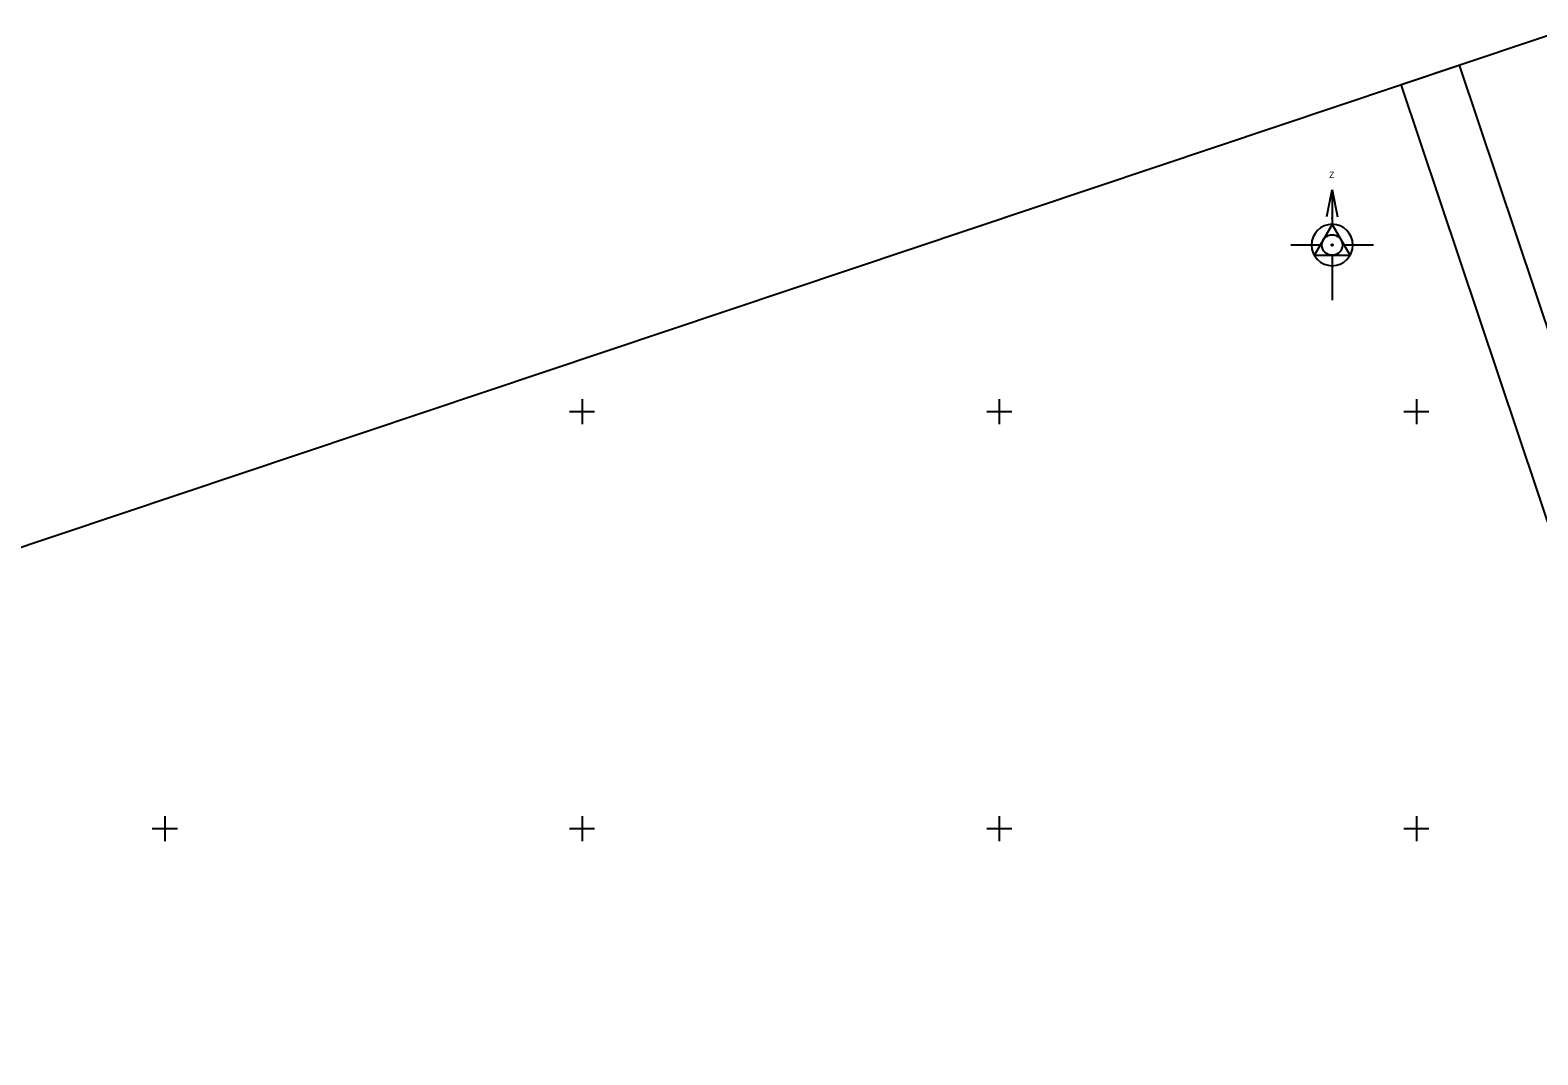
# Model space of a CAD drawing. Extents: x 469981 to 472086, y 246785 to 247785.
# Drawn here: x 470833.9 to 471014.5, y 247272.9 to 247395.7 of the extents above; entities that cross this region are included whole.
import ezdxf

# ---------------------------------------------------------------- set-up
doc = ezdxf.new("R2010")
doc.units = 0
doc.layers.add('GEOD_ELEM_####_####_#', color=7, linetype='Continuous')
doc.layers.add('RAMI_PLAN_####_TKST_#', color=7, linetype='Continuous')

msp = doc.modelspace()

# ---------------------------------------------------------------- linework, layer by layer
at = {"layer": 'GEOD_ELEM_####_####_#'}
for p, q in [((470900, 247351.5), (470900, 247350)), ((470950, 247351.5), (470950, 247350)), ((471000, 247351.5), (471000, 247350)), ((470898.5, 247350), (470900, 247350)), ((470900, 247350), (470900, 247348.5)), ((470900, 247350), (470901.5, 247350)), ((470948.5, 247350), (470950, 247350)), ((470950, 247350), (470950, 247348.5)), ((470950, 247350), (470951.5, 247350)), ((470998.5, 247350), (471000, 247350)), ((471000, 247350), (471000, 247348.5)), ((471000, 247350), (471001.5, 247350)), ((470848.5, 247300), (470850, 247300)), ((470850, 247301.5), (470850, 247300)), ((470850, 247300), (470850, 247298.5)), ((470850, 247300), (470851.5, 247300)), ((470898.5, 247300), (470900, 247300)), ((470900, 247301.5), (470900, 247300)), ((470900, 247300), (470900, 247298.5)), ((470900, 247300), (470901.5, 247300)), ((470948.5, 247300), (470950, 247300)), ((470950, 247301.5), (470950, 247300)), ((470950, 247300), (470950, 247298.5)), ((470950, 247300), (470951.5, 247300)), ((470998.5, 247300), (471000, 247300)), ((471000, 247301.5), (471000, 247300)), ((471000, 247300), (471000, 247298.5)), ((471000, 247300), (471001.5, 247300))]:
    msp.add_line(p, q, dxfattribs=at)
at = {"layer": 'RAMI_PLAN_####_TKST_#'}
for p, q in [((470989.28, 247373.39), (470989.9, 247376.56)), ((470989.9, 247376.56), (470990.53, 247373.35)), ((470989.9, 247376.56), (470989.9, 247372.43)), ((470989.9, 247372.43), (470987.76, 247368.72)), ((470989.9, 247373.26), (470989.9, 247373.09)), ((470989.9, 247373.09), (470989.9, 247373.26)), ((470989.9, 247373.26), (470989.9, 247373.09)), ((470989.9, 247372.43), (470992.04, 247368.72)), ((470988.47, 247369.96), (470984.95, 247369.96)), ((470992.04, 247368.72), (470987.76, 247368.72)), ((470989.9, 247368.72), (470989.9, 247363.36)), ((470994.85, 247369.96), (470991.32, 247369.96))]:
    msp.add_line(p, q, dxfattribs=at)
for points in [[(471602.97, 247280.79), (471091.91, 247109.48), (470998.16, 247389.19), (471509.21, 247560.49)], [(471098.89, 247111.82), (470587.83, 246940.52), (470494.08, 247220.22), (471005.13, 247391.53)]]:
    msp.add_lwpolyline(points, close=True, dxfattribs=at)
for radius in [1.23, 0.0872]:
    msp.add_circle((470989.9, 247369.96), radius, dxfattribs=at)
for start, end in [(90, 270), (270, 90)]:
    msp.add_arc((470989.9, 247369.96), 2.48, start, end, dxfattribs=at)

# ---------------------------------------------------------------- texts
msp.add_text('Z', height=0.75, dxfattribs=at).set_placement((470989.54, 247377.99))

doc.saveas('drawing.dxf')
